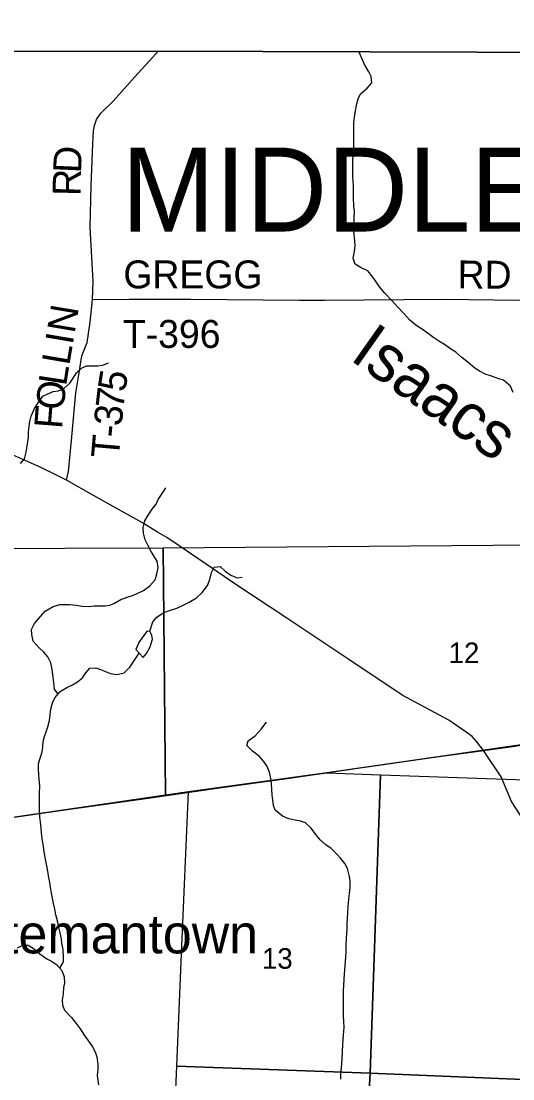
# Model space of a CAD drawing. Extents: x 1759416 to 2214760, y 252598 to 1116833.
# Drawn here: x 1943242 to 1948521, y 917809 to 929159 of the extents above; entities that cross this region are included whole.
import ezdxf

# ---------------------------------------------------------------- set-up
doc = ezdxf.new("R2010")
doc.units = 0
for name, color, linetype in [('GM_X_Adjacent_County', 7, 'Continuous'), ('GM_X_County', 7, 'Continuous'), ('GM_X_County_Road', 7, 'Continuous'), ('GM_X_Minor_Lake', 7, 'Continuous'), ('GM_X_Minor_River', 7, 'Continuous'), ('GM_X_Minor_River_Text', 7, 'Continuous'), ('GM_X_Section', 7, 'Continuous'), ('GM_X_Section_Text', 7, 'Continuous'), ('GM_X_Township', 7, 'Continuous'), ('GM_X_Township_Road', 7, 'Continuous'), ('GM_X_Township_Road_Text', 7, 'Continuous'), ('GM_X_Township_Text', 7, 'Continuous'), ('GM_X_Unincorporated_Text', 7, 'Continuous')]:
    doc.layers.add(name, color=color, linetype=linetype)

msp = doc.modelspace()

# ---------------------------------------------------------------- linework, layer by layer
at = {"layer": 'GM_X_Adjacent_County'}
msp.add_lwpolyline([(1959742, 928940), (1957476, 928914), (1955313, 928900), (1953542, 928878), (1952146, 928858), (1951568, 928828), (1949992, 928829), (1949281, 928821), (1944689, 928838), (1941462, 928831), (1934664, 928840), (1934122, 928828), (1934121, 929197), (1934107, 931513), (1934114, 935137), (1934115, 935394), (1934113, 935746), (1934134, 936040), (1934141, 936112), (1934165, 936177), (1934187, 936214), (1934202, 936590), (1934195, 936859), (1934067, 942157)], dxfattribs=at)
at = {"layer": 'GM_X_County'}
msp.add_lwpolyline([(1931168, 914595), (1931473, 919044), (1931337, 919032), (1928787, 918701), (1928802, 923466), (1928806, 926508), (1928810, 928443), (1928810, 928882), (1933789, 928831), (1934122, 928828), (1934664, 928840), (1941462, 928831), (1944689, 928838), (1949281, 928821), (1949992, 928829), (1951568, 928828), (1952146, 928858), (1953542, 928878), (1955313, 928900), (1957476, 928914), (1959742, 928940)], dxfattribs=at)
at = {"layer": 'GM_X_County_Road'}
for points in [[(1943730, 924234), (1943614, 924290), (1943446, 924372), (1942991, 924571)], [(1948740, 920428), (1948505, 920784), (1948395, 921050), (1948205, 921332), (1948134, 921426), (1948083, 921481), (1948020, 921530), (1947832, 921658), (1947333, 921927), (1946760, 922310), (1946093, 922751), (1945547, 923114), (1945227, 923331), (1944948, 923521), (1944804, 923619), (1944706, 923676), (1944545, 923774), (1944351, 923882), (1944018, 924067), (1943730, 924234)]]:
    msp.add_lwpolyline(points, dxfattribs=at)
at = {"layer": 'GM_X_Minor_Lake'}
for points in [[(1944553, 922331), (1944587, 922373), (1944627, 922443), (1944651, 922527), (1944645, 922571), (1944623, 922611), (1944591, 922609), (1944543, 922549), (1944505, 922491), (1944473, 922415)], [(1944473, 922415), (1944553, 922331)]]:
    msp.add_lwpolyline(points, dxfattribs=at)
at = {"layer": 'GM_X_Minor_River'}
for points in [[(1946827, 928179), (1946847, 928271), (1946859, 928325), (1946885, 928379), (1946955, 928441), (1947007, 928495), (1947000, 928564), (1946975, 928614), (1946927, 928692), (1946872, 928826)], [(1948524, 925174), (1948494, 925240), (1948420, 925306), (1948370, 925322), (1948290, 925348), (1948224, 925372), (1948171, 925398), (1948113, 925435), (1948037, 925499), (1947973, 925551), (1947907, 925605), (1947851, 925643), (1947785, 925687), (1947725, 925725), (1947673, 925762), (1947615, 925802), (1947539, 925856), (1947479, 925898), (1947415, 925950), (1947351, 926022), (1947285, 926091), (1947221, 926161), (1947147, 926241), (1947090, 926307), (1947052, 926361), (1947018, 926412), (1946962, 926478), (1946892, 926512), (1946828, 926552), (1946806, 926616), (1946820, 926686), (1946826, 926751), (1946824, 926801), (1946812, 926901), (1946814, 926965), (1946818, 927037), (1946819, 927120), (1946815, 927170), (1946811, 927262), (1946809, 927338), (1946809, 927392), (1946803, 927491), (1946801, 927545), (1946801, 927619), (1946803, 927671), (1946809, 927733), (1946815, 927805), (1946815, 927874), (1946813, 927940), (1946813, 928072), (1946819, 928128), (1946827, 928179)], [(1943236, 924413), (1943276, 924463), (1943296, 924535), (1943310, 924623), (1943320, 924691), (1943322, 924750), (1943328, 924808), (1943334, 924862), (1943349, 924918), (1943385, 925002), (1943423, 925062), (1943475, 925133), (1943529, 925159), (1943585, 925183), (1943643, 925193), (1943699, 925215), (1943765, 925275), (1943801, 925327), (1943837, 925385), (1943890, 925435), (1943944, 925459), (1943996, 925459), (1944064, 925461), (1944120, 925467), (1944180, 925492)], [(1943639, 921937), (1943601, 921990), (1943593, 922060), (1943587, 922118), (1943575, 922200), (1943559, 922273), (1943529, 922337), (1943485, 922387), (1943435, 922435), (1943371, 922507), (1943355, 922578), (1943353, 922630), (1943385, 922696), (1943448, 922770), (1943500, 922828), (1943584, 922878), (1943658, 922900), (1943762, 922898), (1943834, 922890), (1943898, 922880), (1943972, 922878), (1944024, 922884), (1944145, 922884), (1944195, 922890), (1944245, 922912), (1944313, 922954), (1944379, 922976), (1944437, 922995), (1944489, 923015), (1944555, 923049), (1944623, 923099), (1944679, 923163), (1944700, 923227), (1944712, 923291), (1944702, 923363), (1944642, 923460), (1944604, 923528), (1944574, 923592), (1944554, 923664), (1944550, 923725), (1944568, 923797), (1944606, 923857), (1944650, 923921), (1944690, 923977), (1944714, 924027), (1944764, 924100), (1944796, 924150)], [(1944623, 922611), (1944657, 922714), (1944699, 922764), (1944765, 922810), (1944834, 922836), (1944912, 922860), (1944980, 922890), (1945044, 922922), (1945124, 922972), (1945186, 923028), (1945244, 923101), (1945266, 923167), (1945286, 923243), (1945314, 923299), (1945377, 923305), (1945433, 923255), (1945493, 923215), (1945561, 923185), (1945613, 923193)], [(1943656, 918996), (1943696, 919064), (1943698, 919116), (1943692, 919196), (1943680, 919262), (1943674, 919312), (1943660, 919377), (1943648, 919431), (1943634, 919491), (1943614, 919569), (1943602, 919629), (1943588, 919690), (1943578, 919746), (1943566, 919804), (1943558, 919862), (1943548, 919916), (1943534, 919986), (1943528, 920038), (1943514, 920111), (1943488, 920241), (1943480, 920307), (1943470, 920363), (1943462, 920446), (1943456, 920500), (1943450, 920564), (1943444, 920620), (1943440, 920692), (1943438, 920748), (1943439, 920799), (1943439, 920871), (1943441, 920951), (1943435, 921023), (1943433, 921073), (1943429, 921132), (1943429, 921194), (1943449, 921262), (1943467, 921318), (1943473, 921368), (1943477, 921430), (1943491, 921482), (1943511, 921533), (1943529, 921585), (1943545, 921655), (1943553, 921715), (1943561, 921775), (1943577, 921843), (1943603, 921896), (1943661, 921964), (1943738, 922010), (1943792, 922036), (1943848, 922070), (1943900, 922112), (1943936, 922166), (1943978, 922216), (1944044, 922220), (1944094, 922200), (1944146, 922180), (1944202, 922160), (1944270, 922146), (1944349, 922166), (1944407, 922228), (1944510, 922376)], [(1946673, 917806), (1946675, 917860), (1946681, 917928), (1946688, 918022), (1946692, 918105), (1946696, 918175), (1946700, 918229), (1946704, 918279), (1946708, 918363), (1946706, 918419), (1946704, 918488), (1946702, 918562), (1946704, 918624), (1946704, 918750), (1946706, 918810), (1946710, 918879), (1946714, 918933), (1946718, 918983), (1946724, 919065), (1946730, 919173), (1946732, 919248), (1946736, 919314), (1946740, 919418), (1946742, 919468), (1946746, 919534), (1946748, 919589), (1946751, 919655), (1946761, 919741), (1946767, 919797), (1946773, 919861), (1946773, 919930), (1946767, 919980), (1946745, 920066), (1946717, 920118), (1946673, 920172), (1946627, 920224), (1946569, 920281), (1946511, 920319), (1946452, 920375), (1946404, 920431), (1946354, 920497), (1946294, 920555), (1946242, 920573), (1946182, 920583), (1946114, 920598), (1946046, 920626), (1945970, 920692), (1945950, 920742), (1945942, 920802), (1945936, 920852), (1945934, 920914), (1945930, 920979), (1945922, 921033), (1945908, 921099), (1945880, 921167), (1945844, 921217), (1945800, 921269), (1945724, 921324), (1945664, 921384), (1945680, 921434), (1945754, 921490), (1945820, 921562), (1945876, 921636)], [(1943201, 919214), (1943261, 919244), (1943317, 919242), (1943372, 919212), (1943444, 919150), (1943518, 919096), (1943568, 919070), (1943620, 919036), (1943680, 918970), (1943702, 918903), (1943706, 918837), (1943698, 918787), (1943692, 918719), (1943682, 918653), (1943686, 918598), (1943706, 918546)], [(1943706, 918546), (1943784, 918468), (1943834, 918402), (1943874, 918344), (1943918, 918278), (1943956, 918223), (1944006, 918151), (1944036, 918099), (1944054, 918045), (1944066, 917965), (1944064, 917911), (1944058, 917844), (1944073, 917745)]]:
    msp.add_lwpolyline(points, dxfattribs=at)
at = {"layer": 'GM_X_Section'}
for points in [[(1939462, 923488), (1944766, 923506), (1944790, 920851), (1942534, 920525), (1939486, 920110)], [(1944766, 923506), (1950078, 923548), (1950078, 923434), (1950098, 921606), (1946525, 921094), (1945038, 920887), (1944790, 920851)], [(1947099, 921072), (1946987, 917871), (1944914, 917946), (1944964, 919151), (1945038, 920887), (1946525, 921094)], [(1947099, 921072), (1952477, 920886), (1952344, 917647), (1946987, 917871)], [(1946987, 917871), (1946673, 912411), (1944656, 912501), (1944659, 912568), (1944737, 914175), (1944812, 915795), (1944895, 917531), (1944914, 917946)], [(1952344, 917647), (1952087, 912177), (1946673, 912411), (1946987, 917871)]]:
    msp.add_lwpolyline(points, close=True, dxfattribs=at)
at = {"layer": 'GM_X_Township'}
msp.add_lwpolyline([(1941462, 928831), (1944689, 928838), (1949281, 928821), (1949992, 928829), (1951568, 928828), (1952146, 928858), (1953542, 928878), (1955313, 928900), (1955324, 926909), (1955315, 926725), (1955313, 926444), (1955321, 922391), (1955985, 922511), (1957798, 922777), (1957760, 921682), (1957585, 915650)], dxfattribs=at)
at = {"layer": 'GM_X_Township_Road'}
for points in [[(1943730, 924234), (1943750, 924325), (1943787, 924698), (1943829, 925171), (1943861, 925365), (1943894, 925568), (1943950, 925709), (1943984, 925929), (1944009, 926172), (1944016, 926364), (1943984, 926949), (1943995, 927392), (1944012, 927837), (1944018, 927983), (1944029, 928040), (1944049, 928102), (1944097, 928172), (1944233, 928303), (1944461, 928562), (1944654, 928772), (1944711, 928836)], [(1944009, 926172), (1944401, 926176), (1945063, 926175), (1946229, 926166), (1946500, 926166), (1947781, 926175), (1948590, 926164), (1950103, 926169), (1951216, 926163)], [(1948205, 921332), (1948492, 921371), (1949121, 921465), (1949879, 921568), (1950548, 921669)], [(1942623, 920548), (1942766, 920566), (1942987, 920592), (1943765, 920701), (1944605, 920822), (1945371, 920931), (1946149, 921038), (1946880, 921147), (1947678, 921259), (1948205, 921332)]]:
    msp.add_lwpolyline(points, dxfattribs=at)

# ---------------------------------------------------------------- texts
at = {"layer": 'GM_X_Minor_River_Text'}
msp.add_text('Isaacs', height=500.1, rotation=324.8755, dxfattribs=at).set_placement((1946758, 925532))
at = {"layer": 'GM_X_Section_Text'}
for s, p in [('12', (1947832, 922270)), ('13', (1945828, 918990))]:
    msp.add_text(s, height=221, rotation=0, dxfattribs=at).set_placement(p)
at = {"layer": 'GM_X_Township_Road_Text'}
for s, rotation, p in [('D', 87.5331, (1943884, 927524)), ('R', 88.5987, (1943878, 927280)), ('GREGG', 0, (1944339, 926291)), ('RD', 359.5064, (1947926, 926291)), ('N', 80.3931, (1943815, 925800)), ('T-396', 0, (1944334, 925652)), ('I', 80.3927, (1943795, 925678)), ('L', 80.4024, (1943758, 925457)), ('L', 81.2662, (1943724, 925236)), ('5', 81.0596, (1944358, 925169)), ('O', 83.799, (1943696, 924977)), ('7', 83.4288, (1944338, 924988)), ('F', 85.5003, (1943680, 924778)), ('3', 84.4753, (1944320, 924806)), ('-', 84.9271, (1944309, 924684)), ('T', 85.0655, (1944290, 924460))]:
    msp.add_text(s, height=300, rotation=rotation, dxfattribs=at).set_placement(p)
at = {"layer": 'GM_X_Township_Text'}
msp.add_text('MIDDLEBURY', height=900, rotation=0, dxfattribs=at).set_placement((1944320, 926901))
at = {"layer": 'GM_X_Unincorporated_Text'}
msp.add_text('Batemantown', height=417, rotation=0, dxfattribs=at).set_placement((1942376, 919155))

doc.saveas('drawing.dxf')
